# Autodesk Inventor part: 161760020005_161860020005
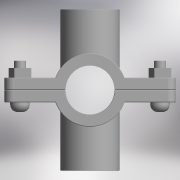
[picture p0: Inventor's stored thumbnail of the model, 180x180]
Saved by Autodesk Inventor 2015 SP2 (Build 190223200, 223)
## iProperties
Created: 2017-05
Part Number: 161760020005_161860020005
Material: Generic
Description: PLASSON DOUBLE SADDLE 20-1/2"
Document SubType Name: Modeling
Designer: KIM
Density: 1 g/cm^3
Appearance: Default
Author: KIM
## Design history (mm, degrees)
derived "16176.ipt"
feature "Solid1::16176.ipt"
feature "Solid2::16176.ipt"
tag "TaggingFeature1"
body "Solid1"
body "Solid2"
other parameters: "d4" = 45, "d5" = 0, "d6" = 3.5, "d8" = 0.1, "d10" = 0, "d11" = 0.2, "d20" = 0.2, "d23" = 0.2, "d36" = 8, "d37" = 6.4, "d38" = 18, "d39" = 0, "d40" = 3, "d41" = 4, "d42" = 0, "d43" = 5, "d44" = 3, "d45" = 0, "d46" = 0.2, "d52" = 18.631, "d53" = 18, "d54" = 0, "d57" = 0, "d58" = 21.6, "d60" = 0, "d62" = 8, "d63" = 22.5, "d66" = 0, "d67" = 66, "d68" = 24.2203, "d69" = 18.631, "d70" = 18, "d71" = 0, "d74" = 0, "d75" = 0.2, "G_" = 18.631, "A_" = 33, "L_1" = 45, "l_2" = 18
